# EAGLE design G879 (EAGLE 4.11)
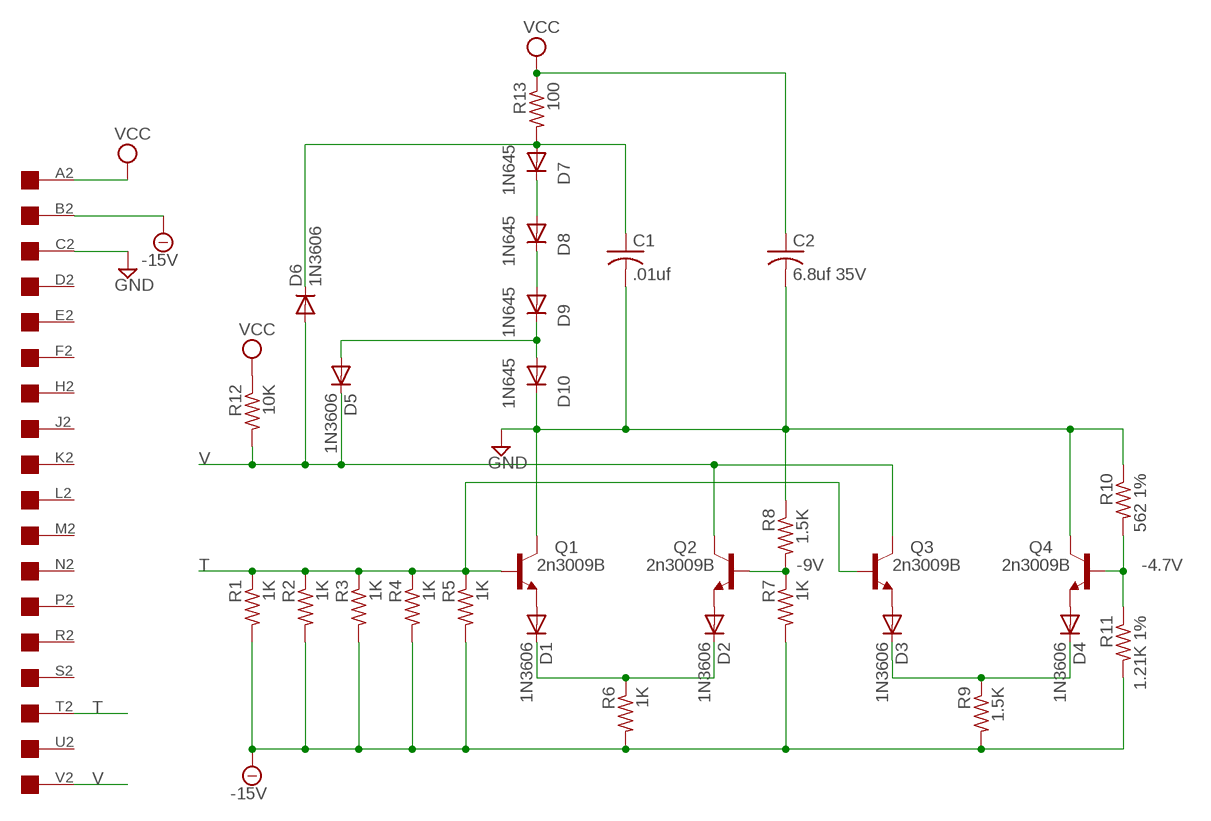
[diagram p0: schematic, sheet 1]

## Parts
C1  .01uf  C-US050-025X075  [C050-025X075]
C2  6.8uf 35V  C-US102-054X133  [C102-054X133]
D1  1N3606  1N4004  [DO41-10]
D2  1N3606  1N4004  [DO41-10]
D3  1N3606  1N4004  [DO41-10]
D4  1N3606  1N4004  [DO41-10]
D5  1N3606  1N4004  [DO41-10]
D6  1N3606  1N4004  [DO41-10]
D7  1N645  1N4004  [DO41-10]
D8  1N645  1N4004  [DO41-10]
D9  1N645  1N4004  [DO41-10]
D10  1N645  1N4004  [DO41-10]
Q1  2n3009B  2N1711  [TO39]
Q2  2n3009B  2N1711  [TO39]
Q3  2n3009B  2N1711  [TO39]
Q4  2n3009B  2N1711  [TO39]
R1  1K  R-US_0207/10  [0207/10]
R2  1K  R-US_0207/10  [0207/10]
R3  1K  R-US_0207/10  [0207/10]
R4  1K  R-US_0207/10  [0207/10]
R5  1K  R-US_0207/10  [0207/10]
R6  1K  R-US_0207/10  [0207/10]
R7  1K  R-US_0207/10  [0207/10]
R8  1.5K  R-US_0207/10  [0207/10]
R9  1.5K  R-US_0207/10  [0207/10]
R10  562 1%  R-US_0207/10  [0207/10]
R11  1.21K 1%  R-US_0207/10  [0207/10]
R12  10K  R-US_0207/10  [0207/10]
R13  100  R-US_0207/10  [0207/10]
U$5  ONE-SIDED  [ONE-SIDED]

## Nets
-4.7V: Q4.2(B) R10.2 R11.1
-9V: Q2.2(B) R7.1 R8.2
-15V: R1.2 R2.2 R3.2 R4.2 R5.2 R6.2 R7.2 R9.2 R11.2 U$5.B2
GND: C1.2 C2.2 D10.C Q1.3(C) Q4.3(C) R8.1 R10.1 U$5.C2
N$1: D1.A Q1.1(E)
N$2: D3.C D4.C R9.1
N$3: D2.A Q2.1(E)
N$4: D4.A Q4.1(E)
N$5: D5.A D9.C D10.A
N$6: D1.C D2.C R6.1
N$7: D8.C D9.A
N$8: D3.A Q3.1(E)
N$9: D7.C D8.A
N$10: C1.1 D6.C D7.A R13.2
T: Q1.2(B) Q3.2(B) R1.1 R2.1 R3.1 R4.1 R5.1 U$5.T2
V: D5.C D6.A Q2.3(C) Q3.3(C) R12.2 U$5.V2
VCC: C2.1 R12.1 R13.1 U$5.A2
Unconnected: U$5.D2 U$5.E2 U$5.F2 U$5.H2 U$5.J2 U$5.K2 U$5.L2 U$5.M2 U$5.N2 U$5.P2 U$5.R2 U$5.S2 U$5.U2

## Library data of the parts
C1 C2 = rcl:C-US: CAPACITOR, American symbol
D1-D10 = diode:1N4004: DIODE
Q1-Q4 = transistor-npn:2N1711: NPN Transistor
R1-R13 = rcl:R-US_: RESISTOR, American symbol
U$5 = con-dec:ONE-SIDED: One-sided DEC Flip-Chip single card fingers

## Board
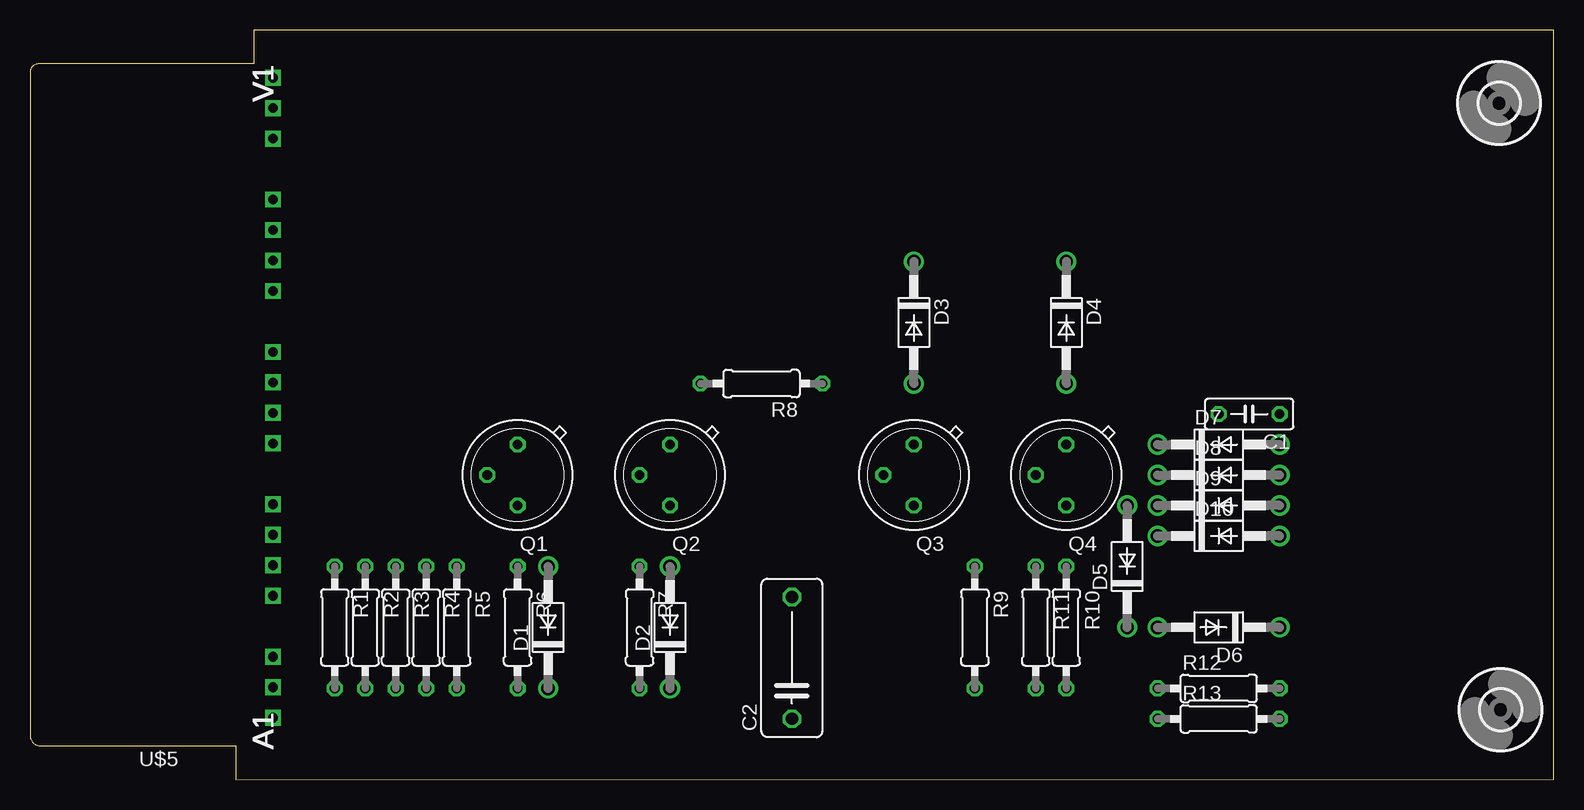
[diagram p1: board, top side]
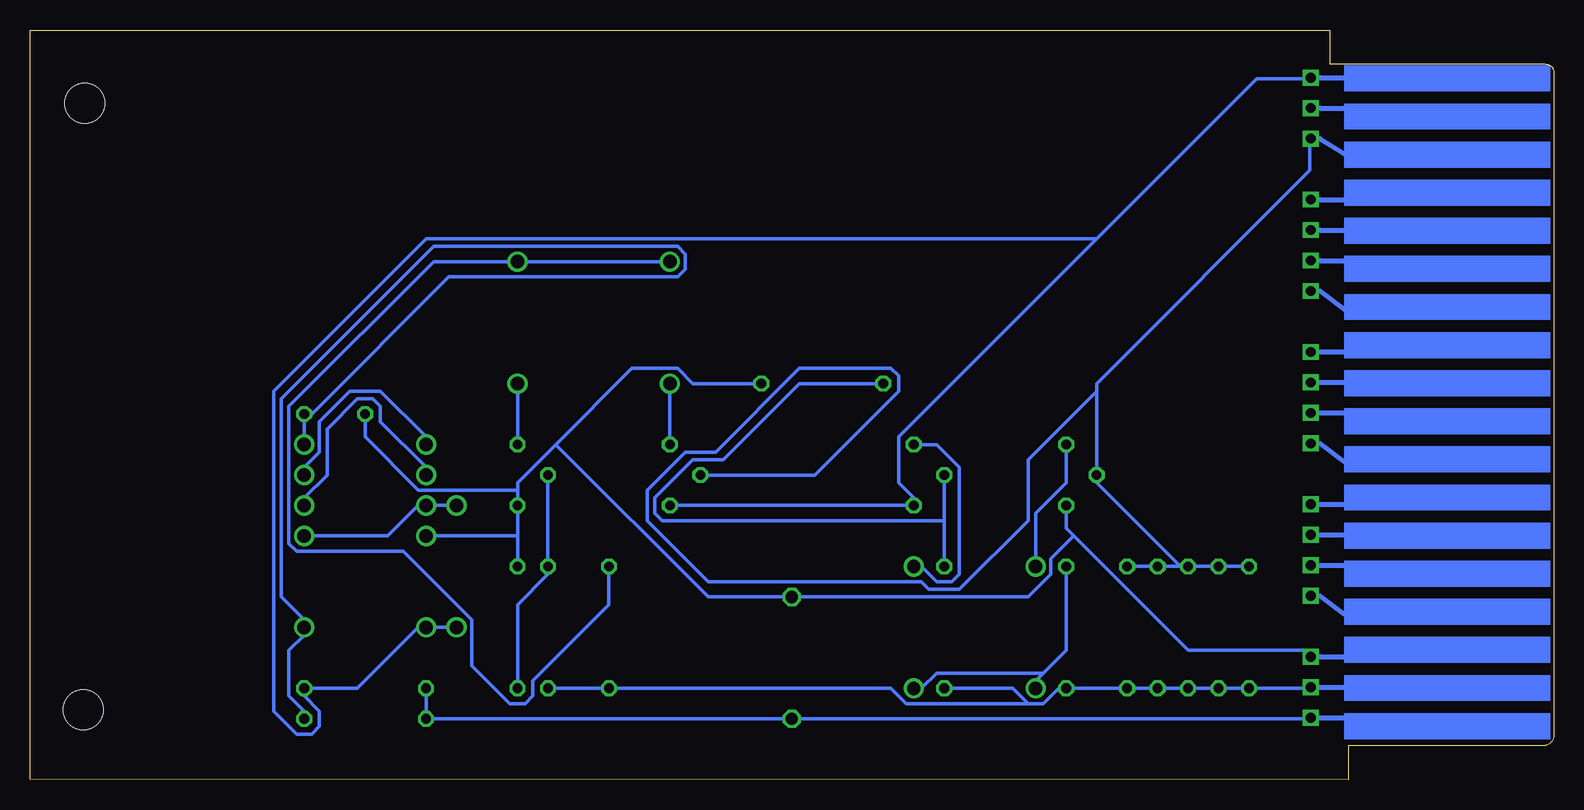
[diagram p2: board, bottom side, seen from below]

Size 126.98 x 62.48 mm. Coordinates in mm from the lower left corner, seen from the top.
Outline: 17.14,2.83 17.14,0 126.98,0.04 126.98,62.45 18.66,62.48 18.66,59.65 0.69,59.65 arc90 0,58.96 0,3.72 arc90 0.89,2.83 17.14,2.83
Copper layers (1*16): Top 0.035mm / dielectric 1.5mm / Bottom 0.035mm
Design rules "10mils": minimum track width 12mil, minimum drill 28mil, track to track 10mil, track to pad 10mil, pad to pad 10mil, via to via 10mil, smd to smd 10mil, copper to edge 40mil, drill to drill 10mil, minimum pad ring 10mil, minimum via ring 8mil, stop-mask expansion 0mil, vias tented up to drill 0mil, thermal gap 10mil

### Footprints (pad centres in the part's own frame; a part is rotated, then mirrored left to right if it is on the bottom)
C050-025X075 = drill 0.813 octagon: 1 -2.54,0; 2 2.54,0
C102-054X133 = drill 1.016 octagon: 1 -5.08,0; 2 5.08,0
DO41-10 = drill 1.118 round: A 5.08,0; C -5.08,0
TO39 = drill 0.813 octagon: 1 0,-2.54; 2 2.54,0; 3 0,2.54
0207/10 = drill 0.813 octagon: 1 -5.08,0; 2 5.08,0
3,3 = hole 3.3: 0,0
ONE-SIDED = drill 0.813 square: A2 20.256,5.175; B2 20.256,7.715; C2 20.256,10.255; D2 20.256,15.335; E2 20.256,17.875; F2 20.256,20.415; H2 20.256,22.955; J2 20.256,28.035; K2 20.256,30.575; L2 20.256,33.115; M2 20.256,35.655; N2 20.256,40.735; P2 20.256,43.275; R2 20.256,45.815; S2 20.256,48.355; T2 20.256,53.435; U2 20.256,55.975; V2 20.256,58.515

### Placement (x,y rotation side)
C1  101.59,30.48 180 top
C2  63.49,10.16 90 top
D1  43.17,12.7 90 top
D2  53.34,12.7 90 top
D3  73.66,38.1 270 top
D4  86.36,38.1 270 top
D5  91.44,17.78 90 top
D6  99.06,12.7 180 top
D7  99.06,27.94 0 top
D8  99.06,25.4 0 top
D9  99.06,22.86 0 top
D10  99.06,20.32 0 top
Q1  40.63,25.4 180 top
Q2  53.34,25.4 180 top
Q3  73.66,25.4 180 top
Q4  86.36,25.4 180 top
R1  25.39,12.7 270 top
R2  27.94,12.7 270 top
R3  30.48,12.7 270 top
R4  33.02,12.7 270 top
R5  35.55,12.7 270 top
R6  40.63,12.7 270 top
R7  50.79,12.7 270 top
R8  60.95,33.02 180 top
R9  78.73,12.7 270 top
R10  86.36,12.7 270 top
R11  83.81,12.7 270 top
R12  99.06,7.62 0 top
R13  99.06,5.08 0 top
U$2  [3,3]  122.42,56.39 0 top
U$3  [3,3]  122.55,5.84 0 top
U$5  -0.01,0 0 top

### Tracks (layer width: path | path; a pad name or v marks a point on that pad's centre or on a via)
-4.7V
  Bottom 0.305: Q4.2 83.81,24.77 83.81,18.41 R11.1 83.81,17.14 86.36,14.61 86.36,8.26 R10.2
-9V
  Bottom 0.305: 50.79,21.59 50.79,24.77 Q2.2 | 50.79,21.59 50.79,18.41 R7.1 | 50.79,21.59 74.29,21.59 74.93,22.23 74.93,23.5 71.75,26.67 69.21,26.67 62.86,33.02 56.51,33.02 R8.2
-15V
  Bottom 0.305: R11.2 83.18,7.62 79.37,7.62 R9.2 78.1,7.62 55.24,7.62 53.97,6.35 43.81,6.35 | U$5.B2 20.32,7.62 24.76,7.62 R1.2 26.03,7.62 27.3,7.62 R2.2 28.57,7.62 29.84,7.62 R3.2 31.11,7.62 32.38,7.62 R4.2 33.65,7.62 34.92,7.62 R5.2 36.19,7.62 40,7.62 R6.2 41.27,7.62 42.54,6.35 43.81,6.35 | 43.81,6.35 45.08,7.62 50.16,7.62 R7.2
GND
  Bottom 0.305: 40,20.32 40.63,20.95 40.63,22.23 Q1.3 | 40,20.32 30.48,10.79 20.32,10.79 U$5.C2 | 86.36,20.32 86.36,22.23 Q4.3 86.36,23.5 86.36,24.13 | 86.36,20.32 86.36,18.41 R10.1 | 83.18,27.94 86.36,24.77 86.36,24.13 | 83.18,27.94 76.83,34.29 73.02,34.29 71.75,33.02 66.67,33.02 R8.1 | 86.36,24.13 94.61,24.13 99.06,28.57 99.06,29.84 C1.2 | 83.18,27.94 70.48,15.24 64.13,15.24 C2.2 62.86,15.24 43.81,15.24 41.9,17.14 41.9,18.41 40,20.32 | 86.36,20.32 93.34,20.32 D10.C
N$1
  Bottom 0.305: Q1.1 40.63,27.3 40.63,24.77 43.17,22.23 43.17,18.41 D1.A
N$2
  Bottom 0.305: R9.1 78.73,17.14 78.73,14.61 85.09,8.26 85.09,6.99 85.72,6.35 86.99,6.35 90.17,9.53 90.17,13.34 95.88,19.05 104.77,19.05 105.41,19.68 105.41,31.11 93.34,43.18 86.99,43.18 D4.C 85.72,43.18 74.29,43.18 D3.C
N$3
  Bottom 0.305: Q2.1 52.7,27.94 51.43,27.94 49.52,26.04 49.52,17.14 50.16,16.51 51.43,16.51 52.7,17.78 D2.A
N$4
  Bottom 0.305: Q4.1 86.36,28.57 86.36,32.38 D4.A
N$5
  Bottom 0.305: D5.A 92.07,22.86 93.34,22.86 D9.C 94.61,22.86 97.15,20.32 103.5,20.32 D10.A
N$6
  Bottom 0.305: 42.54,8.89 43.17,8.26 D1.C | 42.54,8.89 40.63,10.79 40.63,17.14 R6.1 | 42.54,8.89 51.43,8.89 52.7,7.62 D2.C
N$7
  Bottom 0.305: D8.C 93.98,26.04 97.79,29.84 97.79,31.11 98.42,31.75 99.69,31.75 102.23,29.21 102.23,25.4 104.14,23.5 D9.A
N$8
  Bottom 0.305: Q3.1 73.66,28.57 73.66,32.38 D3.A
N$9
  Bottom 0.305: D7.C 93.98,28.57 97.79,32.38 100.33,32.38 102.87,29.84 102.87,27.3 104.14,26.04 D8.A
N$10
  Bottom 0.305: D7.A 104.14,28.57 104.14,29.84 C1.1 103.5,30.48 92.07,41.91 73.02,41.91 72.39,42.55 72.39,43.81 73.02,44.45 93.34,44.45 106.04,31.75 106.04,15.24 104.14,13.34 D6.C 104.14,12.06 105.41,10.79 105.41,6.99 104.14,5.71 R13.2
T
  Bottom 0.305: R1.1 26.03,17.78 27.3,17.78 R2.1 28.57,17.78 29.84,17.78 R3.1 | 31.11,17.78 32.38,17.78 R4.1 33.65,17.78 34.92,17.78 R5.1 | R3.1 31.11,17.78 | 31.11,17.78 38.09,24.77 Q1.2 38.09,26.04 38.09,32.38 | R3.1 31.11,17.78 | 38.09,32.38 38.09,33.02 20.32,50.8 20.32,53.34 U$5.T2 | 38.09,32.38 43.81,26.67 43.81,21.59 49.52,15.88 52.06,15.88 52.7,16.51 70.48,16.51 75.56,21.59 75.56,24.13 72.39,27.3 69.84,27.3 62.86,34.29 55.24,34.29 54.6,33.66 54.6,32.38 61.59,25.4 70.48,25.4 Q3.2
V
  Bottom 0.305: D5.C 92.07,12.7 93.34,12.7 D6.A 94.61,12.7 99.69,7.62 103.5,7.62 R12.2 104.14,6.99 102.87,5.71 102.87,4.45 103.5,3.81 104.77,3.81 106.68,5.71 106.68,32.38 93.98,45.09 38.09,45.09 | 38.09,45.09 54.6,28.57 54.6,24.77 53.34,23.5 Q2.3 53.97,22.86 73.02,22.86 Q3.3 | 38.09,45.09 24.76,58.42 20.32,58.42 U$5.V2
VCC
  Bottom 0.305: R12.1 93.98,6.99 93.98,5.71 R13.1 93.34,5.08 64.13,5.08 C2.1 62.86,5.08 20.32,5.08 U$5.A2

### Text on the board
tNames: V1 | V1 | V1 | V1 | V1 | V1 | V1 | V1 | V1 | V1 | V1 | V1 | V1 | V1 | V1 | V1 | V1 | V1 | V1 | V1 | V1 | V1 | V1 | V1 | V1 | V1 | V1 | V1 | V1 | V1 | V1 | V1 | A1 | A1 | A1 | A1 | A1 | A1 | A1 | A1 | A1 | A1 | A1 | A1 | A1 | A1 | A1 | A1 | A1 | A1 | A1 | A1 | A1 | A1 | A1 | A1 | A1 | A1 | A1 | A1 | A1 | A1 | A1 | A1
